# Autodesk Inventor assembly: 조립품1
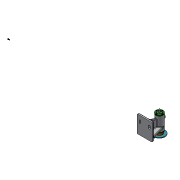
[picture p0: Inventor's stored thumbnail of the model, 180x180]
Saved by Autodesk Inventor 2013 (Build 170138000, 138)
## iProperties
Created: 2019-10
Part Number: 조립품1
Document SubType Name: Assembly
Designer: default
Author: default
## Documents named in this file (18)
- C:\Users\default.default-PC\Desktop\491004V1024\조립품1.iam
- C:\Users\default.default-PC\Desktop\491004V1024\본체.ipt
- C:\Users\default.default-PC\Desktop\491004V1024\슬리브.ipt
- C:\Users\default.default-PC\Desktop\491004V1024\중공축.ipt
- C:\Users\default.default-PC\Desktop\491004V1024\나사.ipt
- C:\Users\default.default-PC\Desktop\491004V1024\센터홀더.ipt
- C:\Users\default.default-PC\Desktop\491004V1024\멈춤나사 M3.ipt
- C:\Users\default.default-PC\Desktop\491004V1024\센터.ipt
- C:\Users\default.default-PC\Desktop\491004V1024\커버.ipt
- C:\Users\default.default-PC\Desktop\491004V1024\부시.ipt
- C:\Users\default.default-PC\Desktop\491004V1024\키 4 x 4 x 10.ipt
- C:\Users\default.default-PC\Desktop\491004V1024\나사축.ipt
- C:\Users\default.default-PC\Desktop\491004V1024\플랜지.ipt
- C:\Users\default.default-PC\Desktop\491004V1024\돌림판.ipt
- C:\Users\default.default-PC\Desktop\491004V1024\와셔.ipt
- C:\Users\default.default-PC\Desktop\491004V1024\너트 M8.ipt
- C:\Users\default.default-PC\Desktop\491004V1024\핸들.ipt
- C:\Users\default.default-PC\Desktop\491004V1024\볼트 M3.ipt
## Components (2 placed, 2 different names)
1. 플랜지:1
2. 핸들:1 — 플러쉬:4
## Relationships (1: Flush 1)
- 플러쉬:4 [Flush]: 핸들:1
